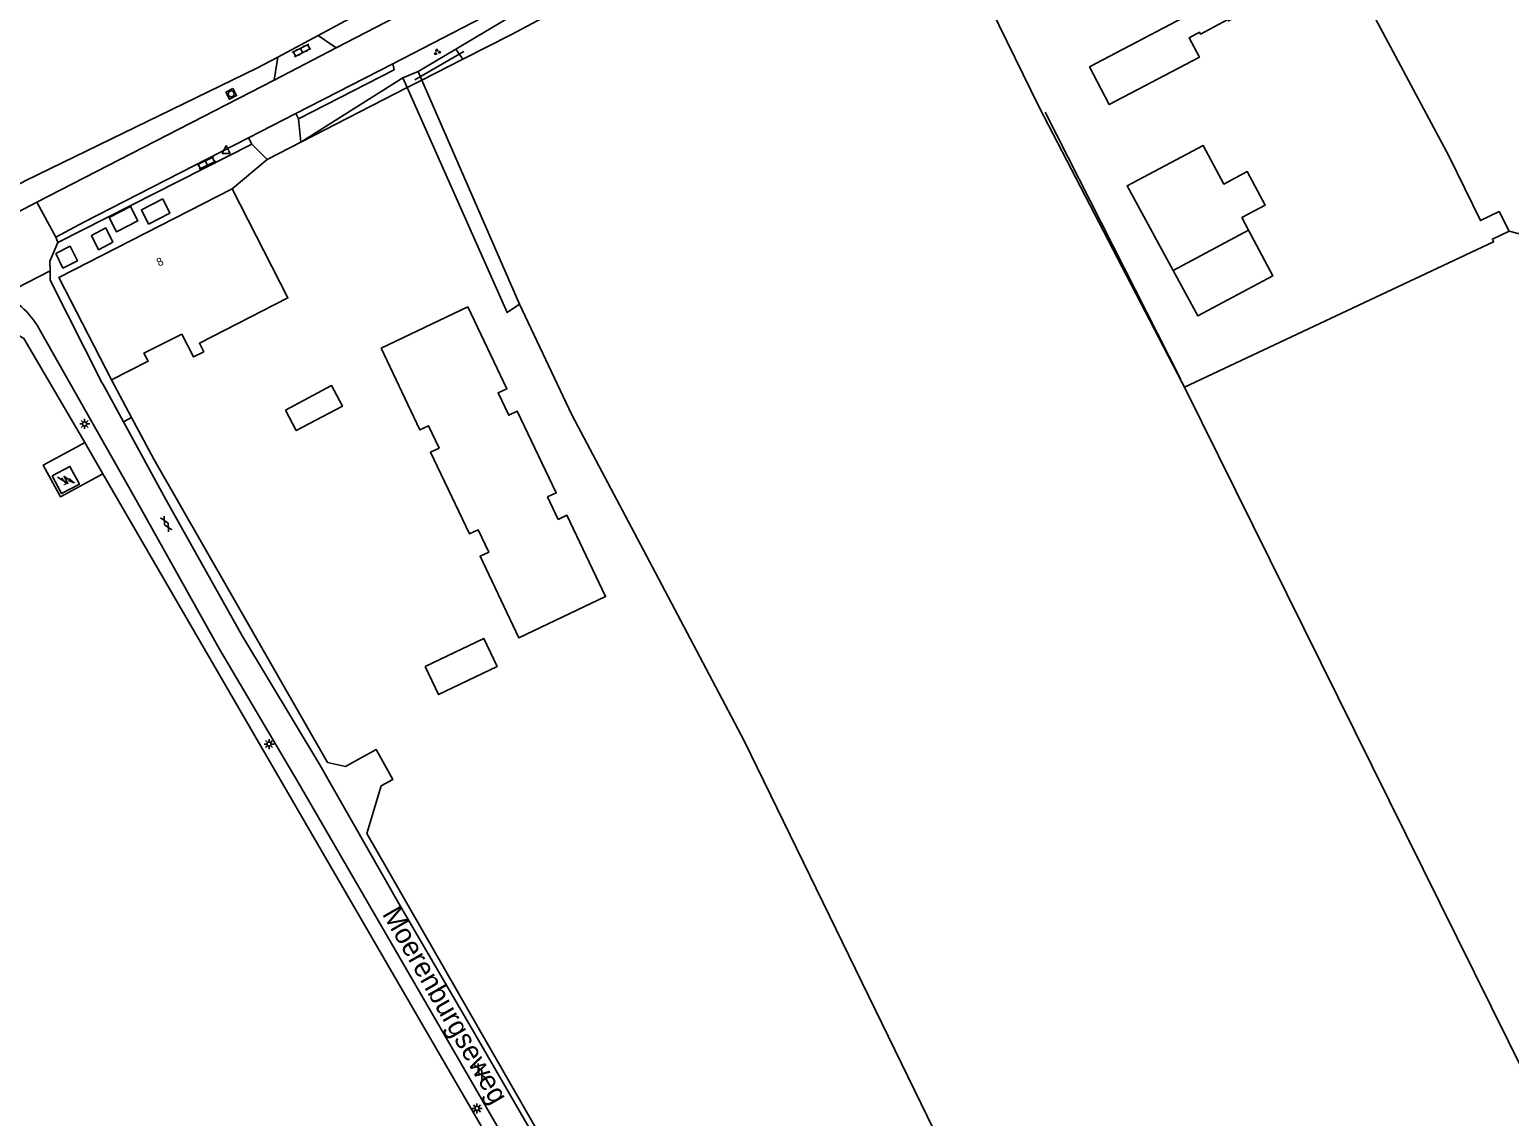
# Model space of a CAD drawing. Extents: x 135999 to 138000, y 396000 to 398501.
# Drawn here: x 136164 to 136349, y 396720.9 to 396856.7 of the extents above; entities that cross this region are included whole.
import ezdxf

# ---------------------------------------------------------------- set-up
doc = ezdxf.new("R2010")
doc.units = 0
for name, color, linetype in [('gg-afsc-draadraster', 7, 'Continuous'), ('gg-afsc-erfafscheiding', 7, 'Continuous'), ('gg-afsc-hekwerk', 7, 'Continuous'), ('gg-afsc-lijn draadraster', 7, 'Continuous'), ('gg-afsc-muur', 7, 'Continuous'), ('gg-anno-huisnummerreeks BGT', 7, 'Continuous'), ('gg-anno-openbare ruimte label', 7, 'Continuous'), ('gg-bbg-bijgebouw', 7, 'Continuous'), ('gg-bbg-gedigitaliseerde bijgebouw', 7, 'Continuous'), ('gg-bbg-hoofdgebouw', 7, 'Continuous'), ('gg-bbg-open loods', 7, 'Continuous'), ('gg-knt-bronhoudergrens', 7, 'Continuous'), ('gg-knt-verharding', 7, 'Continuous'), ('gg-kntw-bovenkant insteek waterloop', 7, 'Continuous'), ('gg-kwrk-duiker nz buis', 7, 'Continuous'), ('gt-grn-groengrens', 7, 'Continuous'), ('gt-grn-groengrens NZ', 7, 'Continuous'), ('gt-grn-weggrens', 7, 'Continuous'), ('gt-symb-gesloten verharding', 7, 'Continuous'), ('gt-symb-groenvak', 7, 'Continuous'), ('gt-symb-klinker verharding', 7, 'Continuous'), ('gt-symb-lichtmast', 7, 'Continuous'), ('gt-symb-rioolschacht', 7, 'Continuous'), ('gt-symb-trafo symbool', 7, 'Continuous'), ('gt-symb-waterafsluiter', 7, 'Continuous'), ('gx-grn-maaiveld', 7, 'Continuous')]:
    doc.layers.add(name, color=color, linetype=linetype)

# ---------------------------------------------------------------- blocks, each defined once
blk = doc.blocks.new('gt0-LMAST')
at = {"layer": 'gt-symb-lichtmast'}
for p, q in [((-0.18, 0.17), (-0.45, 0.44)), ((-0.01, 0.25), (-0.01, 0.62)), ((0.17, 0.17), (0.44, 0.44)), ((-0.26, 0), (-0.63, 0)), ((-0.18, -0.18), (-0.45, -0.45)), ((-0.01, -0.25), (-0.01, -0.63)), ((0.44, -0.45), (0.17, -0.18)), ((0.24, 0), (0.62, 0))]:
    blk.add_line(p, q, dxfattribs=at)
blk.add_circle((-0.01, 0), 0.25, dxfattribs=at)
blk = doc.blocks.new('gt0-GESVH1')
at = {"layer": 'gt-symb-gesloten verharding'}
for p, q in [((-0.99, -0.26), (0.01, 0.24)), ((0.01, -0.26), (-0.99, 0.24)), ((0.01, 0.24), (1.01, -0.26)), ((1.01, 0.24), (0.01, -0.26))]:
    blk.add_line(p, q, dxfattribs=at)
blk = doc.blocks.new('gt0-KL1')
at = {"layer": 'gt-symb-klinker verharding'}
for p, q in [((-1.15, 0.3), (1.15, 0.3)), ((-1, -0.3), (-1, 0.3)), ((-0.5, 0.3), (-0.5, 0.45)), ((0, -0.3), (0, 0.3)), ((0.5, 0.3), (0.5, 0.45)), ((1, -0.3), (1, 0.3)), ((-1.15, -0.3), (1.15, -0.3)), ((-0.5, -0.45), (-0.5, -0.3)), ((0.5, -0.45), (0.5, -0.3))]:
    blk.add_line(p, q, dxfattribs=at)
blk = doc.blocks.new('gt0-WAFSL')
at = {"layer": 'gt-symb-waterafsluiter'}
for p, q in [((-0.5, -0.33), (0, 0.67)), ((0, 0.67), (0.5, -0.33)), ((0.5, -0.33), (-0.5, -0.33))]:
    blk.add_line(p, q, dxfattribs=at)
blk = doc.blocks.new('gt0-RS')
at = {"layer": 'gt-symb-rioolschacht'}
blk.add_lwpolyline([(-0.5, -0.5), (0.5, -0.5), (0.5, 0.5), (-0.5, 0.5)], close=True, dxfattribs=at)
blk.add_circle((0, 0), 0.375, dxfattribs=at)
blk = doc.blocks.new('gt0-GRVAK')
at = {"layer": 'gt-symb-groenvak'}
for p, q in [((-0.11, 0.19), (-0.23, 0.24)), ((-0.18, 0.15), (0.09, 0.15)), ((-0.09, 0.21), (-0.16, 0.32)), ((-0.05, 0.21), (-0.05, 0.39)), ((0, 0.21), (0.06, 0.32)), ((0.02, 0.19), (0.13, 0.24)), ((0.26, -0.05), (0.2, 0.06)), ((0.3, -0.05), (0.3, 0.13)), ((0.35, -0.05), (0.41, 0.06)), ((-0.24, -0.23), (-0.36, -0.18)), ((-0.32, -0.26), (-0.05, -0.26)), ((-0.23, -0.21), (-0.29, -0.1)), ((-0.18, -0.2), (-0.18, -0.02)), ((-0.14, -0.21), (-0.07, -0.1)), ((-0.12, -0.23), (0, -0.18)), ((0.24, -0.07), (0.12, -0.02)), ((0.17, -0.11), (0.44, -0.11)), ((0.37, -0.07), (0.49, -0.02))]:
    blk.add_line(p, q, dxfattribs=at)
blk = doc.blocks.new('gt0-HSP')
at = {"layer": 'gt-symb-trafo symbool'}
for points in [[(0.77, 0.75), (-0.53, 0), (0.47, 0), (-0.83, -0.75)], [(-0.22, -0.24), (-0.83, -0.75), (-0.08, -0.48)]]:
    blk.add_lwpolyline(points, dxfattribs=at)

msp = doc.modelspace()

# ---------------------------------------------------------------- linework, layer by layer
at = {"layer": 'gg-afsc-draadraster'}
msp.add_line((136170.91, 396805.12), (136169.87, 396804.56), dxfattribs=at)
for points in [[(136306.92, 396899.77), (136317.97, 396882.54), (136328.63, 396864.8), (136331.55, 396859.34), (136341.43, 396840.86), (136345.33, 396832.86), (136347.66, 396834), (136348.94, 396831.55)], [(136308.35, 396812.04), (136346.97, 396830.22), (136346.82, 396830.55), (136348.94, 396831.55)], [(136348.94, 396831.55), (136352.13, 396830.73)], [(136169.87, 396804.56), (136165.68, 396802.29), (136167.83, 396798.34), (136173.13, 396801.21)]]:
    msp.add_lwpolyline(points, dxfattribs=at)
at = {"layer": 'gg-afsc-erfafscheiding'}
for p, q in [((136174.21, 396812.95), (136176.73, 396808.27)), ((136176.73, 396808.27), (136179.53, 396803.06))]:
    msp.add_line(p, q, dxfattribs=at)
msp.add_lwpolyline([(136192.41, 396851.91), (136163.52, 396837.87), (136161.9, 396837.01)], dxfattribs=at)
at = {"layer": 'gg-afsc-hekwerk'}
msp.add_line((136290.91, 396846.41), (136307.85, 396813.07), dxfattribs=at)
msp.add_lwpolyline([(136264.73, 396654.11), (136263, 396657.14), (136263.52, 396659.25), (136260.98, 396663.67), (136259.04, 396664.05), (136206.13, 396756.27), (136207.93, 396762.21), (136209.4, 396763.03), (136207.3, 396766.78), (136203.49, 396764.65)], dxfattribs=at)
at = {"layer": 'gg-afsc-lijn draadraster'}
msp.add_line((136170.91, 396805.12), (136169.87, 396804.56), dxfattribs=at)
msp.add_lwpolyline([(136169.87, 396804.56), (136165.68, 396802.29), (136167.83, 396798.34), (136173.13, 396801.21)], dxfattribs=at)
at = {"layer": 'gg-afsc-muur'}
msp.add_lwpolyline([(136179.53, 396803.06), (136201.23, 396765.14), (136203.49, 396764.65)], dxfattribs=at)
at = {"layer": 'gg-bbg-bijgebouw'}
msp.add_line((136316.35, 396831.66), (136306.92, 396826.64), dxfattribs=at)
for points in [[(136316.35, 396831.66), (136319.39, 396825.98), (136309.99, 396820.98), (136306.92, 396826.64)], [(136207.95, 396816.93), (136212.76, 396806.71), (136213.84, 396807.23), (136215.18, 396804.43), (136214.09, 396803.92), (136218.96, 396793.71), (136220.04, 396794.22), (136221.38, 396791.42), (136220.29, 396790.91), (136225.15, 396780.71), (136235.99, 396785.87), (136231.14, 396796.04), (136230.06, 396795.52), (136228.73, 396798.32), (136229.81, 396798.83), (136224.95, 396809.04), (136223.88, 396808.53), (136222.55, 396811.33), (136223.64, 396811.84), (136218.78, 396822.08), (136207.95, 396816.93)]]:
    msp.add_lwpolyline(points, dxfattribs=at)
at = {"layer": 'gg-bbg-gedigitaliseerde bijgebouw'}
for points in [[(136195.96, 396809.19), (136197.31, 396806.62), (136203.09, 396809.67), (136201.74, 396812.24), (136195.96, 396809.19)], [(136213.43, 396777.13), (136215.1, 396773.63), (136222.43, 396777.12), (136220.77, 396780.63), (136213.43, 396777.13)]]:
    msp.add_lwpolyline(points, dxfattribs=at)
at = {"layer": 'gg-bbg-hoofdgebouw'}
for points in [[(136314.62, 396867.17), (136306.73, 396863.03), (136309.02, 396858.67), (136296.48, 396852.07), (136298.93, 396847.37), (136310.2, 396853.3), (136308.93, 396855.72), (136310.21, 396856.4), (136310.33, 396856.18), (136313.76, 396857.98), (136313.84, 396857.83), (136314.98, 396858.43), (136314.9, 396858.58), (136318.32, 396860.38), (136314.62, 396867.17)], [(136189.31, 396836.83), (136167.66, 396825.75), (136174.21, 396812.95)], [(136189.31, 396836.83), (136196.28, 396823.21), (136185.21, 396817.54), (136185.75, 396816.48), (136184.47, 396815.83), (136183.02, 396818.66), (136178.28, 396816.31), (136178.8, 396815.29), (136174.21, 396812.95)], [(136166.8, 396800.95), (136167.99, 396798.74), (136170.22, 396799.93), (136169.03, 396802.14), (136166.8, 396800.95)]]:
    msp.add_lwpolyline(points, dxfattribs=at)
at = {"layer": 'gg-bbg-open loods'}
msp.add_lwpolyline([(136306.92, 396826.64), (136301.17, 396837.22), (136310.69, 396842.24), (136313.27, 396837.42), (136316.18, 396838.98), (136318.43, 396834.8), (136315.51, 396833.24), (136316.35, 396831.66)], dxfattribs=at)
at = {"layer": 'gg-knt-bronhoudergrens'}
for p, q in [((136308.03, 396812.68), (136308.35, 396812.04)), ((136308.35, 396812.04), (136353.63, 396720.54))]:
    msp.add_line(p, q, dxfattribs=at)
msp.add_lwpolyline([(136273.01, 396882.11), (136290.18, 396847.05), (136308.03, 396812.68)], dxfattribs=at)
at = {"layer": 'gg-knt-verharding'}
for p, q in [((136209.39, 396852.44), (136271.05, 396884.57)), ((136220.52, 396863.9), (136202.3, 396854.45)), ((136202.3, 396854.45), (136200.05, 396856.01)), ((136202.3, 396854.45), (136194.56, 396850.43)), ((136195, 396853.3), (136194.56, 396850.43)), ((136209.39, 396852.44), (136197.28, 396846.24)), ((136164.9, 396835.15), (136194.56, 396850.43)), ((136197.28, 396846.24), (136191.34, 396843.21)), ((136197.61, 396845.6), (136197.88, 396842.66)), ((136167.5, 396830.12), (136191.75, 396842.4)), ((136191.34, 396843.21), (136170.75, 396832.68)), ((136191.75, 396842.4), (136193.69, 396840.51)), ((136147.84, 396826.36), (136164.9, 396835.15)), ((136167.26, 396830.79), (136170.75, 396832.68)), ((136167.5, 396830.12), (136167.26, 396830.79)), ((136175.71, 396807.72), (136173.17, 396812.38))]:
    msp.add_line(p, q, dxfattribs=at)
for points in [[(136209.39, 396852.44), (136209.54, 396851.71), (136197.61, 396845.6)], [(136176.62, 396834.64), (136173.95, 396833.27), (136174.83, 396831.47), (136177.5, 396832.83), (136176.62, 396834.64)], [(136180.64, 396835.58), (136177.97, 396834.2), (136178.87, 396832.42), (136181.53, 396833.8), (136180.64, 396835.58)], [(136173.51, 396831.94), (136171.73, 396831.01), (136172.62, 396829.23), (136174.39, 396830.16), (136173.51, 396831.94)], [(136167.5, 396830.12), (136166.52, 396827.8), (136166.55, 396826.57)], [(136167.26, 396828.74), (136168.16, 396826.93), (136169.97, 396827.85), (136169.05, 396829.65), (136167.26, 396828.74)], [(136173.17, 396812.38), (136173.02, 396812.65), (136166.57, 396825.44), (136166.55, 396826.57)], [(136165.57, 396818.65), (136177.11, 396798.3), (136187.72, 396779.32), (136197.52, 396762.71), (136218.82, 396725.97), (136236.15, 396695.92), (136240.03, 396689.14)], [(136280.11, 396625.63), (136266.86, 396648.93), (136247.81, 396682.04), (136229.34, 396714.43), (136219.63, 396731.22), (136210.15, 396747.5), (136200.28, 396764.83), (136190.52, 396781.03), (136181, 396797.99), (136175.71, 396807.72)]]:
    msp.add_lwpolyline(points, dxfattribs=at)
msp.add_arc((136154.35, 396812.9), 12.61, 27.1486, 58.7167, dxfattribs=at)
at = {"layer": 'gg-kntw-bovenkant insteek waterloop'}
for p, q in [((136218.14, 396853.05), (136217.27, 396854.31)), ((136212.54, 396851.49), (136210.62, 396850.72)), ((136213, 396850.42), (136212.54, 396851.49)), ((136210.62, 396850.72), (136211.17, 396849.48)), ((136225.22, 396822.42), (136213, 396850.42))]:
    msp.add_line(p, q, dxfattribs=at)
for points in [[(136217.27, 396854.31), (136223.35, 396857.92), (136272.11, 396883.58), (136273.01, 396882.11)], [(136218.14, 396853.05), (136224.24, 396856.13), (136273.01, 396882.11)], [(136211.17, 396849.48), (136223.68, 396821.37), (136225.22, 396822.42)]]:
    msp.add_lwpolyline(points, dxfattribs=at)
at = {"layer": 'gg-kwrk-duiker nz buis'}
msp.add_line((136212.13, 396850.45), (136218.27, 396853.98), dxfattribs=at)
at = {"layer": 'gt-grn-groengrens'}
for p, q in [((136200.05, 396856.01), (136222.65, 396868.14)), ((136192.41, 396851.91), (136195, 396853.3)), ((136212.54, 396851.49), (136217.27, 396854.31)), ((136213, 396850.42), (136218.14, 396853.05)), ((136197.88, 396842.66), (136210.62, 396850.72)), ((136197.88, 396842.66), (136211.17, 396849.48)), ((136211.17, 396849.48), (136213, 396850.42)), ((136193.69, 396840.51), (136189.31, 396836.83)), ((136170.91, 396805.12), (136173.13, 396801.21)), ((136173.13, 396801.21), (136238.62, 396688.44)), ((136253.31, 396767.83), (136242.21, 396788.84))]:
    msp.add_line(p, q, dxfattribs=at)
for points in [[(136242.21, 396788.84), (136231.78, 396808.59), (136225.22, 396822.42)], [(136293.13, 396685.41), (136279.5, 396714.12), (136253.31, 396767.83)]]:
    msp.add_lwpolyline(points, dxfattribs=at)
at = {"layer": 'gt-grn-groengrens NZ'}
msp.add_line((136175.71, 396807.72), (136176.73, 396808.27), dxfattribs=at)
at = {"layer": 'gt-grn-weggrens'}
for p, q in [((136195, 396853.3), (136200.05, 396856.01)), ((136197.61, 396845.6), (136197.28, 396846.24)), ((136191.75, 396842.4), (136191.34, 396843.21)), ((136193.69, 396840.51), (136197.88, 396842.66)), ((136167.26, 396830.79), (136164.9, 396835.15)), ((136160.9, 396823.67), (136166.55, 396826.57))]:
    msp.add_line(p, q, dxfattribs=at)
at = {"layer": 'gx-grn-maaiveld'}
msp.add_lwpolyline([(136156.2, 396821.26), (136158.04, 396821.39), (136160.82, 396819.61), (136163.28, 396818.14), (136170.91, 396805.12)], dxfattribs=at)

# ---------------------------------------------------------------- block references
at = {"layer": 'gt-symb-gesloten verharding'}
for p, rotation in [((136181.08, 396794.96), -60.66720921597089), ((136220.3, 396726.53), -62.66592414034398)]:
    msp.add_blockref('gt0-GESVH1', p, dxfattribs=dict(at, rotation=rotation))
at = {"layer": 'gt-symb-groenvak'}
msp.add_blockref('gt0-GRVAK', (136214.92, 396853.94), dxfattribs=at)
at = {"layer": 'gt-symb-klinker verharding'}
for p, rotation in [((136197.99, 396854.12), 26.28331291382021), ((136186.08, 396840.06), -154.33212483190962)]:
    msp.add_blockref('gt0-KL1', p, dxfattribs=dict(at, rotation=rotation))
at = {"layer": 'gt-symb-lichtmast'}
for p in [(136170.88, 396807.45), (136193.93, 396767.44), (136219.92, 396721.9)]:
    msp.add_blockref('gt0-LMAST', p, dxfattribs=at)
at = {"layer": 'gt-symb-rioolschacht', "rotation": -152.7431282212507}
msp.add_blockref('gt0-RS', (136189.19, 396848.7), dxfattribs=at)
at = {"layer": 'gt-symb-trafo symbool', "rotation": 118.2813610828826}
msp.add_blockref('gt0-HSP', (136168.52, 396800.48), dxfattribs=at)
at = {"layer": 'gt-symb-waterafsluiter'}
msp.add_blockref('gt0-WAFSL', (136188.56, 396841.57), dxfattribs=at)

# ---------------------------------------------------------------- texts
at = {"layer": 'gg-anno-huisnummerreeks BGT'}
for s, rotation, p in [('8', 27.1, (136180.17, 396827.1)), ('1', 28.3, (136168.17, 396799.69))]:
    msp.add_text(s, height=1, rotation=rotation, dxfattribs=at).set_placement(p)
at = {"layer": 'gg-anno-openbare ruimte label'}
msp.add_text('Moerenburgseweg', height=2.5, rotation=299.9, dxfattribs=at).set_placement((136208, 396746.21))

doc.saveas('drawing.dxf')
